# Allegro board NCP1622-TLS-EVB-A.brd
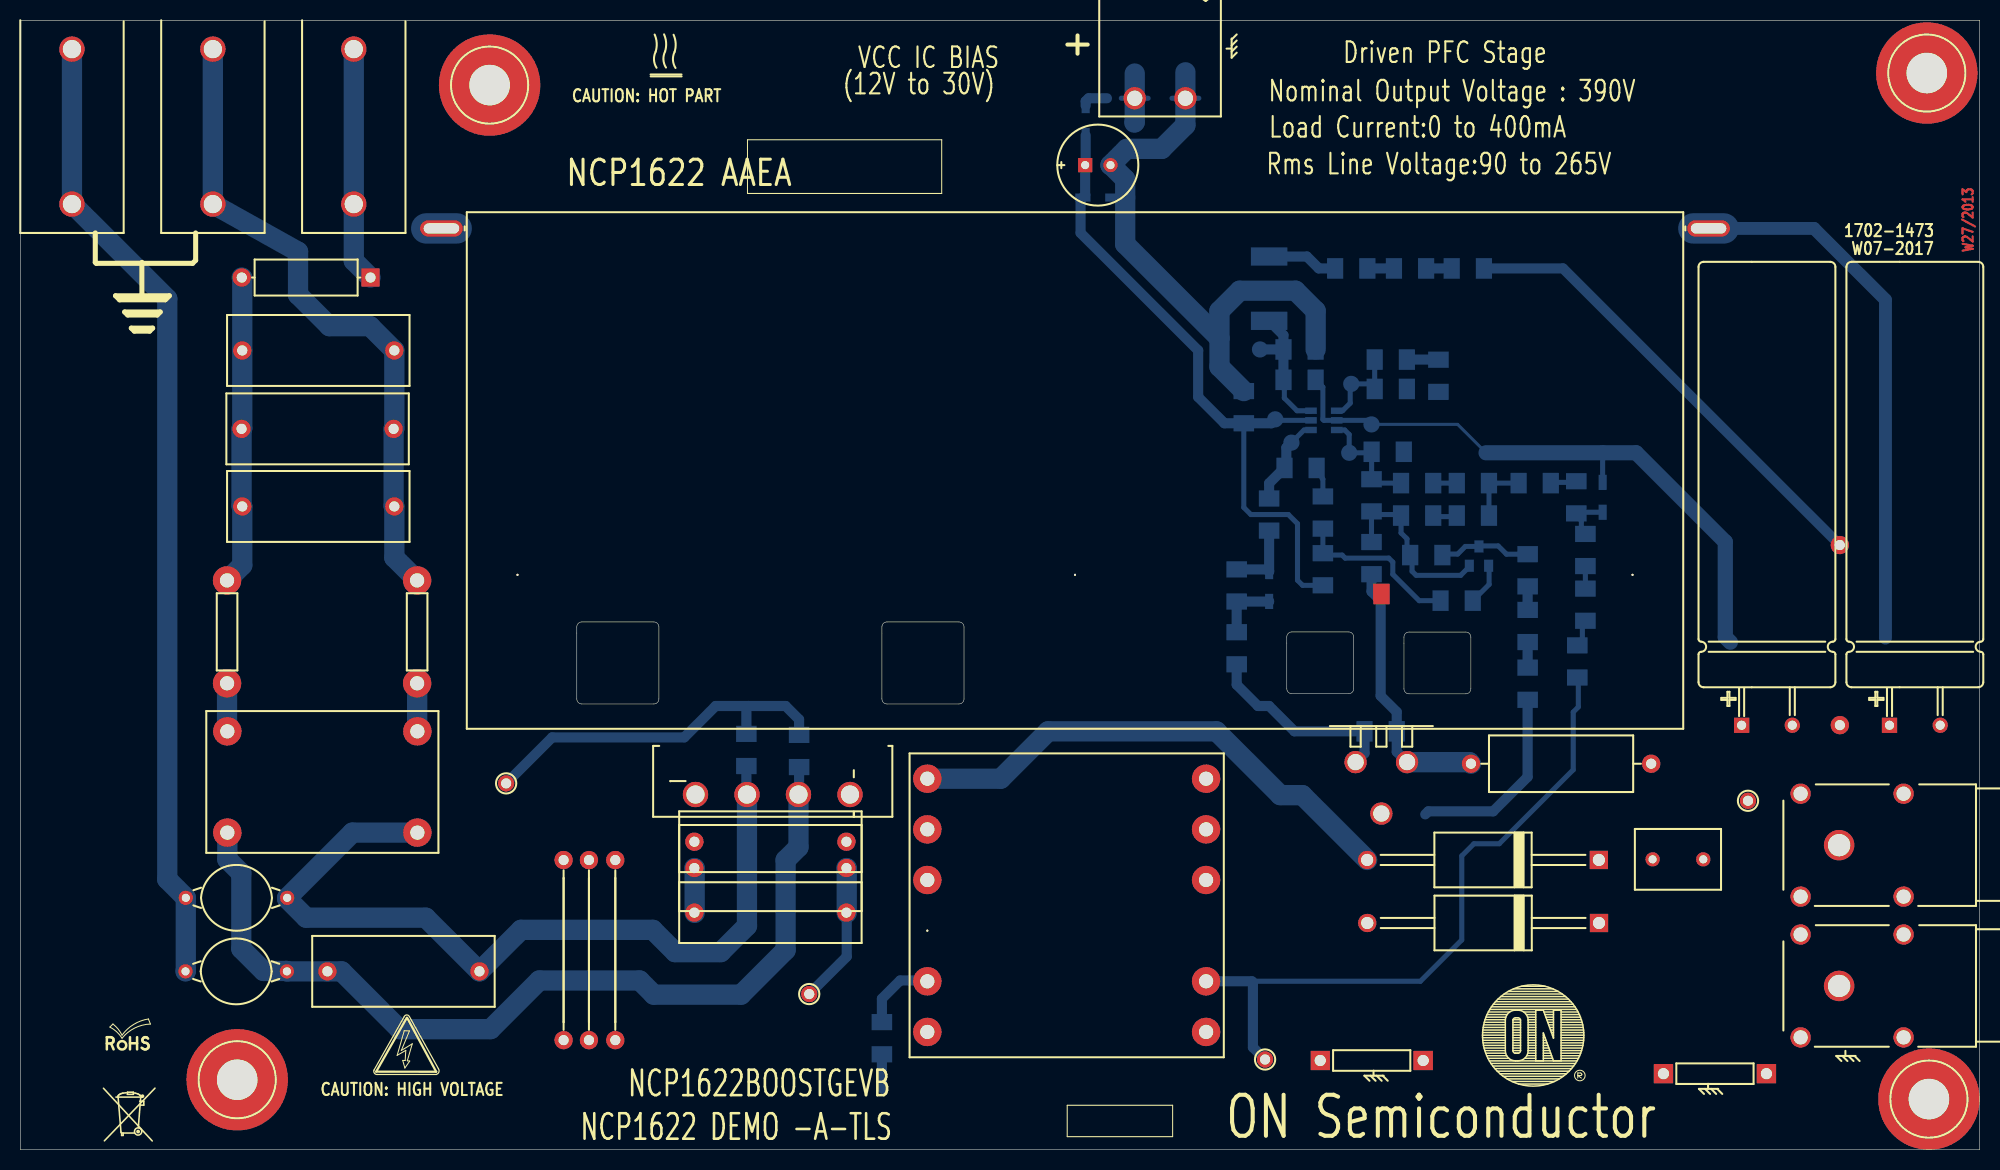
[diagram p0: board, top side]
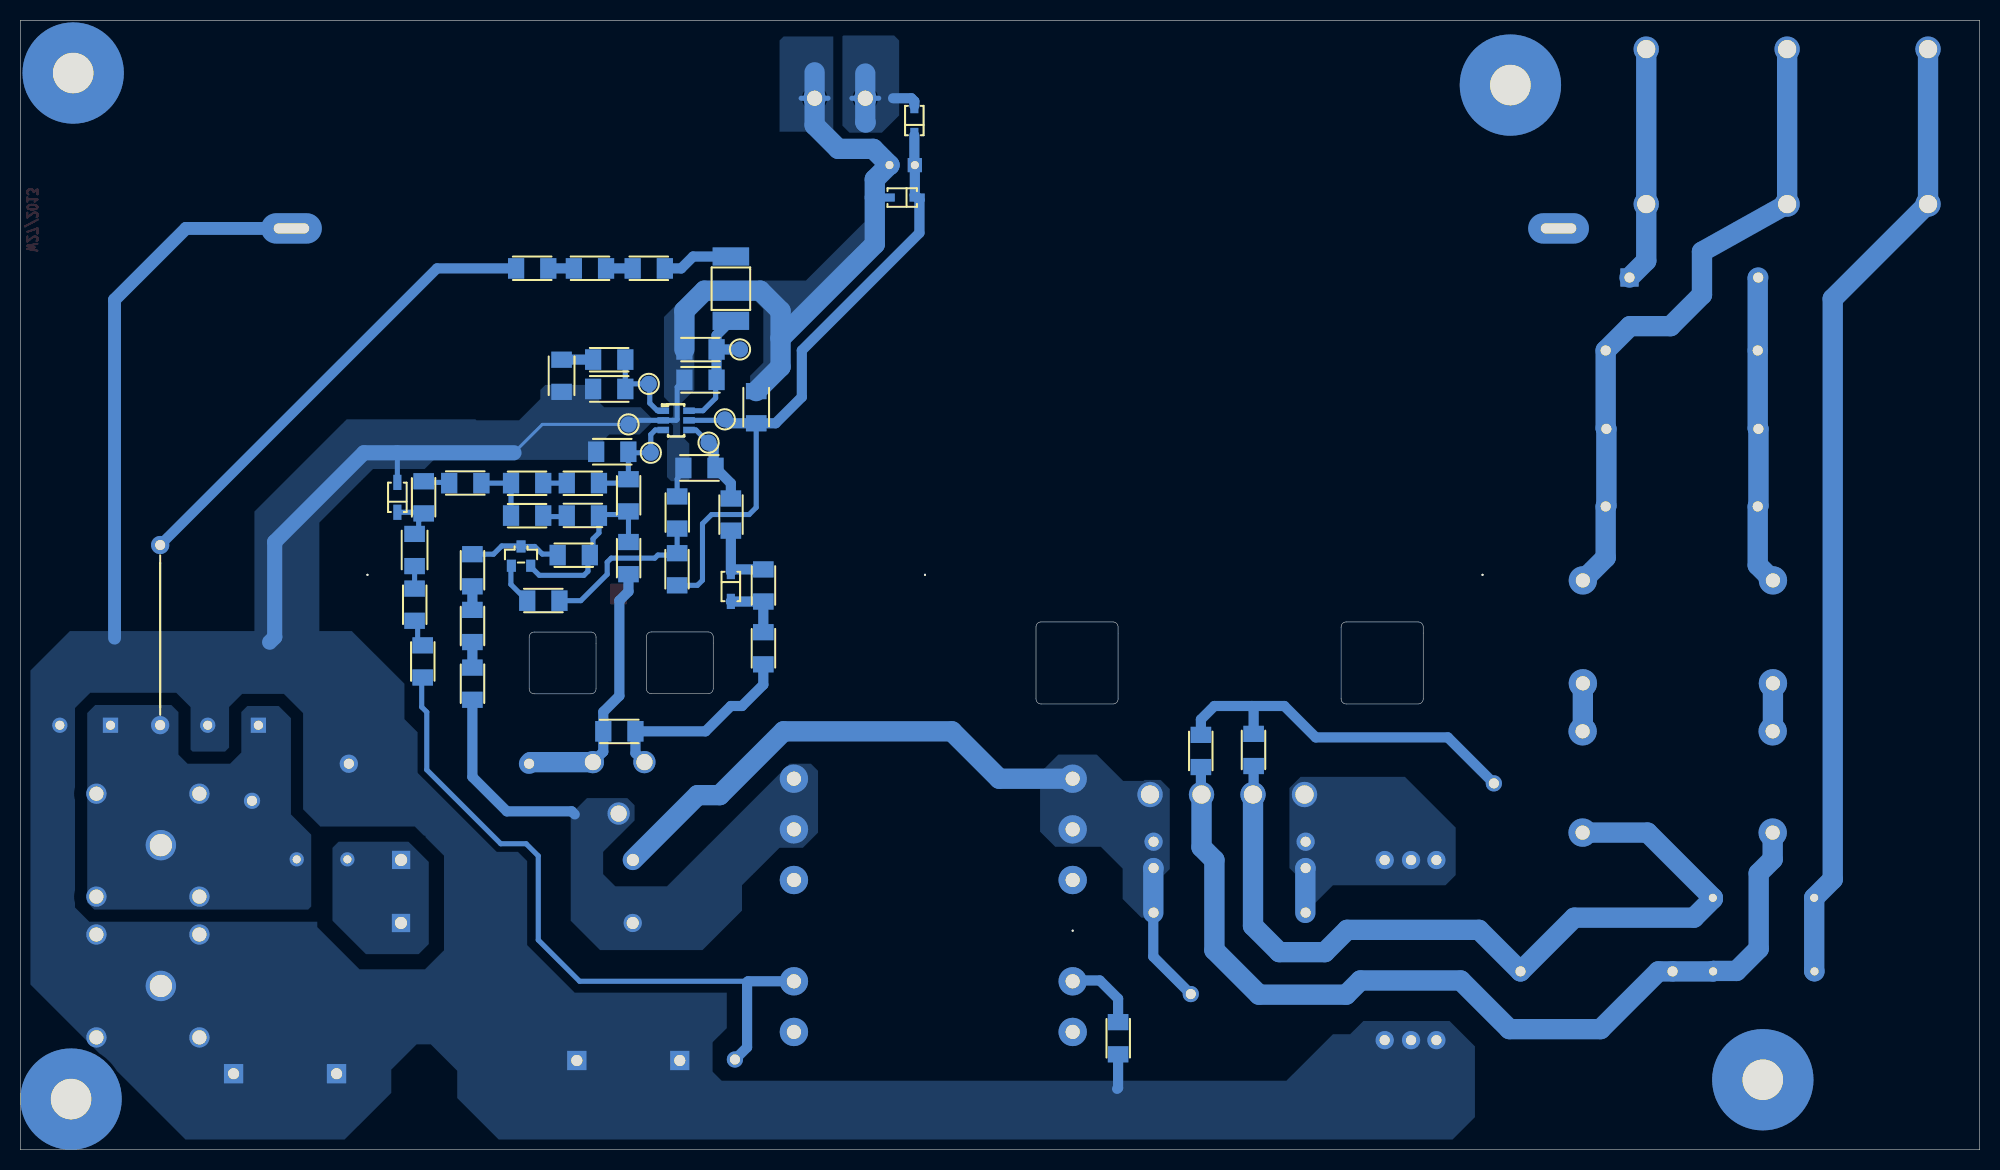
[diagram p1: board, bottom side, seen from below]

Outline 193.3 x 111.5 mm; copper layers: TOP, IN1, IN2, BOTTOM. Coordinates in mm from the lower left corner of the outline.
Outline path: 0,111.5 0,0 193.3,0 193.3,111.5 0,111.5 ; 54.9,51.6 arc(55.05,51.95) 55.4,52.1 62.5,52.1 arc(62.85,51.95) 63,51.6 63,44.5 arc(62.85,44.15) 62.5,44 55.4,44 arc(55.05,44.15) 54.9,44.5 54.9,51.6 ; 85,51.6 arc(85.15,51.95) 85.5,52.1 92.6,52.1 arc(92.95,51.95) 93.1,51.6 93.1,44.5 arc(92.95,44.15) 92.6,44 85.5,44 arc(85.15,44.15) 85,44.5 85,51.6 ; 124.94,50.61 arc(125.09,50.97) 125.44,51.11 131.04,51.11 arc(131.39,50.97) 131.54,50.61 131.54,45.51 arc(131.39,45.16) 131.04,45.01 125.44,45.01 arc(125.09,45.16) 124.94,45.51 124.94,50.61 ; 136.5,50.6 arc(136.65,50.95) 137,51.1 142.6,51.1 arc(142.95,50.95) 143.1,50.6 143.1,45.5 arc(142.95,45.15) 142.6,45 137,45 arc(136.65,45.15) 136.5,45.5 136.5,50.6

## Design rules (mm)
net group MASSE: nets DRV EARTH
net group PHASE1: nets PH1
net group PHASE2: nets PH2

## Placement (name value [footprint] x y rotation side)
C1  1nF/Y  [CAPA_DISK_D7_E7_P10]  21.3 17.6 0 top
C2  1nF/Y  [CAPA_DISK_D7_E7_P10]  21.33 24.86 180 top
C3A  220nF/X2  [CAPA_E7XL18_H13_P15]  29.4 78.9 180 top
C3B  220nF/X2  [CAPA_E7XL18_H13_P15]  29.4 63.5 180 top
C3C  220nF/X2  [CAPA_E7XL18_H13_P15]  29.33 71.16 180 top
C4  220nF/X2  [CAPA_E7XL18_H13_P15]  37.8 17.6 0 top
C5  470nF  [CAPA_E8-5XL18_H14-5_P15]  74 27.8 180 top
C5A  220nF  [CAPA_E6XL18_H11_P15]  74 30.4 180 top
C5B  220nF  [CAPA_E6XL18_H11_P15]  74 23.4 180 top
C6A  68uF  [CAPA_ALU_D12-5_H40_P5_C]  186.9 41.9 90 top
C6B  68uF  [CAPA_ALU_D12-5_H40_P5_C]  172.31 41.9 90 top
C7  22uF  [CAPA_CH_D8_H5_P2-5]  106.3 97.2 0 top
C8  1nF  [1206]  126.2 76 180 bottom
C9  2.2uF  [1206]  139.9 76.4 90 bottom
C10  220nF  [1206]  135.2 75.1 180 bottom
C11  NC  [1206]  134.9 68.9 180 bottom
C12  NC  [1206]  126.3 67.3 180 bottom
C13  100nF  [1206]  120.7 73.3 270 bottom
C30  1nF  [1206]  154.4 59.2 270 bottom
CM1  2x10mH  [SELF__WE_CMC750341634]  29.8 36.3 180 top
CSZCD  TEST POINT  [TP_150_SM]  131.1 68.8 90 bottom
D1  MUR550  [DO201AD]  144.31 22.38 180 top
D2  1N5406  [DO201AD]  144.3 28.6 180 top
D3  1N4148  [SOD123]  123.2 55.6 270 bottom
D4  1N4148  [SOD123]  105.1 101.6 90 bottom
D5  0R  [SMD1206]  153.5 64.4 270 bottom
D6  1N4148  [SOD123]  156.1 64.4 90 bottom
DRV  TEST POINT  [TP_150_SM]  125.4 69.8 90 bottom
DZ2  MMSZ33T1  [SOD123]  106.3 94 0 bottom
EARTH  571-Yelow  [CONN_BANANE-4MM_571]  5.1 101 90 top
F1  4A-250V  [RES_AXI_3-5X10]  28.2 86.1 180 top
FB  TEST POINT  [TP_150_SM]  122.3 79 90 bottom
GND  TEST POINT  [TP_150_SM]  133.3 71.6 90 bottom
HS1  Heatsink_KL_195  [DISIPATEUR_TP207ST_SP]  44.05 41.55 0 top
J4  MSTBA_2_508  [CON_MSTBA_2_508_C]  112.4 103.8 180 top
L  571-black  [CONN_BANANE-4MM_571]  32.9 101 90 top
L2  200uH  [TRANSFO_WE_750370081_EFD30]  103.23 24.12 180 top
N  571-blue  [CONN_BANANE-4MM_571]  19 101 90 top
NOREF  -  []  -73.87 -11.06 0 top
NOREF#2  -  [unnamed#2]  21.4 6.9 0 top
NOREF#3  -  [unnamed#2]  188.29 4.99 0 top
NOREF#4  -  []  0 111.5 0 top
NOREF#5  -  []  -0.7 0 90 top
NOREF#6  -  []  131.1 54.6 0 top
NOREF#7  -  [unnamed#2]  188.08 106.29 0 top
NOREF#8  -  []  78.8 52.7 0 top
NOREF#9  -  [unnamed#2]  46.3 105.1 0 top
NOREF#10  -  []  -164.96 -15.11 0 top
NOREF#11  -  []  294.51 -23.26 180 bottom
P1  SLB4-I/90_R  [BANANE_4MM_SLB4]  179.43 30.06 0 top
P2  SLB4-I/90_B  [BANANE_4MM_SLB4]  179.43 16.16 0 top
Q1  IPA50R250CP  [TO220_C]  131.73 38.26 0 top
Q2  BSS127  [SOT23]  143.9 58.6 0 bottom
R1  1000k  [SMD1206]  71.63 39.46 270 bottom
R2  1000k  [SMD1206]  76.83 39.36 270 bottom
R3  80mR  [RES_LVR03]  152 38.1 0 top
R4  10k  [SMD1206]  134.2 41.3 180 bottom
R5  2.2R  [SMD1206]  120 49.5 90 bottom
R6  22R  [SMD1206]  120 55.7 90 bottom
R7  0R  [SMD1206]  123.2 62.7 90 bottom
R8  680k  [SMD1206]  142.8 87 0 bottom
R9  1800k  [SMD1206]  137.1 87 0 bottom
R10  1800k  [SMD1206]  131.3 87 0 bottom
R11  27k  [SMD1206]  126.2 79 180 bottom
R12  22k  [SMD1206]  135.2 78 180 bottom
R21  47k  [SMD1206]  133.3 58.4 90 bottom
R22  5.1M  [SMD1206]  148.7 46 90 bottom
R23  240K  [SMD1206]  148.7 51.7 90 bottom
R24  240K  [SMD1206]  148.7 57.2 90 bottom
R27  0R  [2512]  123.2 85 270 bottom
R30  0R  [SMD1206]  138.7 58.7 180 bottom
R31  0R  [SMD1206]  133.3 64.6 90 bottom
R32  4.7M  [SMD1206]  128.5 62.9 90 bottom
R33  1M  [SMD1206]  128.5 57.3 270 bottom
R34  NC  [SMD1206]  137.8 62.6 0 bottom
R36  NC  [SMD1206]  137.8 65.8 180 bottom
R37  27k  [SMD1206]  143.3 65.8 180 bottom
R38  22k  [SMD1206]  143.3 62.6 180 bottom
R39  270K  [SMD1206]  149.4 65.8 0 bottom
R40  100R  [SMD1206]  154.4 53.8 90 bottom
R41  NC  [SMD1206]  153.6 48.2 90 bottom
R42  NC  [SMD1206]  141.7 54.2 0 bottom
RTH1  B57153S150M  [DISK_D8-5_E6_P5]  163.53 28.66 0 top
RZ  0R  [SMD1206]  85 11 90 bottom
S1A  Strap  [JUMPER400H]  138.4 8.8 180 top
S1B  Strap  [JUMPER400H]  162.1 7.5 0 top
S2A  Strap  [JUMPER400H]  20.4 56.2 270 top
S2B  Strap  [JUMPER400H]  39.15 56.2 270 top
S3  Strap  [STRAP_FIL_700]  179.5 50.8 90 bottom
S4A  Strap  [STRAP_FIL_700]  53.6 19.7 270 top
S4B  Strap  [STRAP_FIL_700]  56.1 19.7 270 top
S4C  Strap  [STRAP_FIL_700]  58.7 19.7 270 top
U1  GBU406  [PONT_RD_GBU_C]  74.23 35.06 0 top
U2  NCP1602  [SOT23-6]  128.6 72 270 bottom
VAUX  TEST POINT  [TP_T1]  122.8 8.9 0 top
VBULK  TEST POINT  [TP_T1]  170.44 34.44 0 top
VCC  TEST POINT  [TP_150_SM]  123.8 72.1 90 bottom
VCTRL  TEST POINT  [TP_150_SM]  131.3 75.6 90 bottom
VIN  TEST POINT  [TP_T1]  77.83 15.36 0 top
VLINE  TEST POINT  [TP_T1]  47.93 36.16 0 top

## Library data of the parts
C1 C2 C3A C3B C3C C4 C5 C5A C5B C8-C13 C30 = C
C6A C6B = C_elect_1
C7 = C_elect_0
CM1 = WE-CMB_2
CSZCD DRV FB GND S1A S1B S2A S2B S3 S4A S4B S4C VAUX VBULK VCC VCTRL VIN VLINE = TEST POINT_0
D1-D4 D6 = D1N4937
D5 R1-R12 R21-R24 R27 R30-R34 R36-R42 RZ = R
DZ2 = zener_sot23_0
EARTH L N = HEADER 1_1
F1 = FUSE
HS1 = Heatsink_KL_195
J4 = HEADER 2_0
L2 = RN114-0_5.8/02
P1 P2 = HEADER 1_0
Q1 = NMOS_3
Q2 = NMOS_4
RTH1 = THERMISTOR_0
U1 = KBUxK_1
U2 = NCP1602

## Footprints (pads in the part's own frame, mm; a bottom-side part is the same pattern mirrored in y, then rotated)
1206
  rect 1.6x2.03 smd: 1(-1.587,0) 2(1.587,0)
2512
  rect 1.8x3.6 smd: 1(-3.175,0) 2(3.175,0)
BANANE_4MM_SLB4
  round 3 hole 2.2: 1(0,0)
  round 2 hole 1.4: 2(-3.8,5.08) 3(-3.8,-5.08) 4(6.36,5.08) 5(6.36,-5.08)
CAPA_ALU_D12-5_H40_P5_C
  rect 1.5x1.5 hole 0.9: 1(0,2.5)
  round 1.5 hole 0.9: 2(0,-2.5)
CAPA_CH_D8_H5_P2-5
  rect 1.4x1.4 hole 0.8: 1(-1.25,0)
  round 1.4 hole 0.8: 2(1.25,0)
CAPA_DISK_D7_E7_P10
  round 1.4 hole 0.8: 1(-5,0) 2(5,0)
CAPA_E6XL18_H11_P15
  round 1.8 hole 1: 1(7.5,0) 2(-7.5,0)
CAPA_E7XL18_H13_P15
  round 1.8 hole 1: 1(7.5,0) 2(-7.5,0)
CAPA_E8-5XL18_H14-5_P15
  round 1.8 hole 1: 1(7.5,0) 2(-7.5,0)
CON_MSTBA_2_508_C
  round 2.2 hole 1.5: 1(2.46,0) 2(-2.54,0)
CONN_BANANE-4MM_571
  round 2.5 hole 1.8: 1(-7.65,0) 2(7.65,0)
DISIPATEUR_TP207ST_SP
  round 0.2 hole 3.2 unplated: (5,15.2) (60,15.2) (115,15.2)
  oval 4.2x1.6 hole 3.5x1: 1(-2.5,49.4) 2(122.5,49.4)
DISK_D8-5_E6_P5
  round 1.4 hole 0.8: 1(-2.5,0) 2(2.5,0)
DO201AD
  round 1.8 hole 1.2: 1(11.43,0)
  rect 1.8x1.8 hole 1.2: 2(-11.43,0)
JUMPER400H
  round 2.8 hole 1.4: 1(0,0) 2(10.16,0)
PONT_RD_GBU_C
  round 2.5 hole 1.8: 1(7.62,0) 2(2.54,0) 3(-2.54,0) 4(-7.62,0)
RES_AXI_3-5X10
  rect 1.8x1.8 hole 1: 1(-6.35,0)
  round 1.8 hole 1: 2(6.35,0)
RES_LVR03
  round 1.8 hole 1: 1(-8.89,0) 2(8.89,0)
SELF__WE_CMC750341634
  round 2.8 hole 1.4: 1(-9.375,5) 2(-9.375,-5) 3(9.375,-5) 4(9.375,5)
SMD1206
  rect 1.6x2.03 smd: 1(-1.587,0) 2(1.587,0)
SOD123
  rect 1.5x0.8 smd: 1(1.475,0) 2(-1.475,0)
SOT23
  rect 0.9x1.2 smd: 1(0.953,0.953) 2(-0.953,0.953) 3(0,-0.953)
SOT23-6
  rect 0.64x1.15 smd: 1(-0.953,-1.27) 2(0,-1.27) 3(0.953,-1.27) 4(0.953,1.27) 5(0,1.27) 6(-0.953,1.27)
STRAP_FIL_700
  round 1.8 hole 1: 1(-8.89,0) 2(8.89,0)
TO220_C
  rect 1.6x2.03 smd: (2.54,16.6)
  round 2.2 hole 1.6: 1(0,0) 2(2.54,-5.08) 3(5.08,0)
TP_150_SM
  round 1.6 smd: 1(0,0)
TP_T1
  round 1.6 hole 1: 1(0,0)
TRANSFO_WE_750370081_EFD30
  round 0.2 hole 1 unplated: (13.75,2.5)
  round 2.8 hole 1.4: 1(-13.75,12.5) 2(-13.75,7.5) 4(-13.75,-2.5) 5(-13.75,-7.5) 6(-13.75,-12.5) 7(13.75,-12.5) 8(13.75,-7.5) 9(13.75,-2.5) 11(13.75,7.5) 12(13.75,12.5)
unnamed#2
  round 10 hole 4: 1(0,0)

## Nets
GND_EARTH: C6A.2(-) C6B.2(-) C7.2(-) C8.1 C9.1 C10.1 C11.1 C12.1 C13.1 D6.1 DZ2.1(ANODE) GND.1 HS1.2 J4.2 P2.1 P2.2 P2.3 P2.4 P2.5 R3.2 R11.1 R32.2 RZ.1 S1A.1 S1A.2 S1B.1 S1B.2 S4A.2 S4B.2 S4C.2 U2.2(GND)
VCC: C7.1(+) C13.2 D4.2 DZ2.2(CATHODE) R33.2 U2.5(VCC) VCC.1
VIN: C5.2 C5A.2 C5B.2 D2.1 L2.7 L2.8 U1.1(+) VIN.1
CSZCD: C11.2 CSZCD.1 R31.2 R36.2 U2.3(CS/ZCD)
DRIVE: D3.2 R6.2 R7.1
DRV: C12.2 DRV.1 R7.2 U2.4(DRV)
EARTH: C1.1 C2.2 EARTH.1 EARTH.2
FB: C8.2 FB.1 R11.2 R27.2 U2.6(FB)
LINE: F1.1 L.1 L.2
NEUTRAL: C3A.2 C3B.2 C3C.2 N.1 N.2 S2B.1
PH1: C1.2 C4.2 CM1.4 R2.2 U1.2(AC1)
PH2: C2.1 C4.1 CM1.1 R1.2 U1.3(AC2)
VAUX: L2.2 R41.1 VAUX.1
VBULK: C6A.1(+) C6B.1(+) P1.1 P1.2 P1.3 P1.4 P1.5 RTH1.2 S3.1 VBULK.1
VCTRL: C10.2 R12.2 U2.1(VCTRL) VCTRL.1
VDRAIN: D1.1 L2.5 L2.6 Q1.2(D) R22.1
VLINE: R1.1 R2.1 VLINE.1
VSOURCE: Q1.3(S) R3.1 R4.1 R21.1
N292537: CM1.3 S2A.2
N698273: CM1.2 S2B.2
N12234995: C3A.1 C3B.1 C3C.1 F1.2 S2A.1
N12236480: C5.1 C5A.1 C5B.1 S4A.1 S4B.1 S4C.1 U1.4(-)
N12238080: D1.2 D2.2 RTH1.1
N12238999: Q1.1(G) R4.2 R5.1
N12239079: D3.1 R5.2 R6.1
N12239384: D4.1 J4.1
N12240791: C9.2 R12.1
N12241323: Q2.2(S) R21.2 R30.2 R31.1 R34.1
N12242862: R23.2 R24.1
N12244725: R8.2 S3.2
N12257162: L2.11 RZ.2
N12257918: R9.1 R10.2
N12257928: R8.1 R9.2
N12261898: Q2.3(D) R24.2 R30.1
N12263431: C30.1 D5.2 D6.2
N12264127: R37.1 R38.1 R39.1
N12264132: R34.2 R38.2
N12264252: R36.1 R37.2
N12264429: R32.1 R33.1 R42.1
N12264457: Q2.1(G) R42.2
N122408501: R22.2 R23.1
N122410581: R40.1 R41.2
N122446060: R10.1 R27.1
N122633001: C30.2 R40.2
N122636271: D5.1 R39.2

Pads without a net: HS1 1; L2 1 4 9 12; NOREF#2 1; NOREF#3 1; NOREF#7 1; NOREF#9 1

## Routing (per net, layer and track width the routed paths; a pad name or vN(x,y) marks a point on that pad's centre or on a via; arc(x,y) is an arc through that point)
GND_EARTH: length 184.6
  BOTTOM w0.3: DZ2.1 109,94 ; GND.1 141.8,71.6 144.6,68.8
  BOTTOM w0.5: R32.2 128.5,66.2 128.4,66.3 ; 116.27,103.8 J4.2 113.61,103.8 ; D6.1 156.1,68.8 ; C8.1 128.5,75.29 128.5,72.1 128.6,72 U2.2 132.9,72 GND.1
  BOTTOM w1: RZ.1 85,6.1 85.1,6
  BOTTOM w1.27: 184,50.5 184,83.9 176.95,90.95 HS1.2
  BOTTOM w1.5: 168.7,50.1 168.2,50.6 168.2,60 159.4,68.8 144.6,68.8
  BOTTOM w2: C13.1 118.3,77.29 118.3,80.1 ; 118.3,80.1 109,89.4 109,95.8 107.6,97.2 C7.2 109.15,98.8 112.6,98.8 114.94,101.14 J4.2 114.94,106.36 ; 118.3,80.1 118.3,82.8 120.3,84.8 125.8,84.8 127.79,82.81 R11.1
VCC: length 65.8
  BOTTOM w0.5: R33.2 126.5,55.71 126,56.21 126,61.8 125.1,62.7 121.4,62.7 120.7,63.4 C13.2 ; VCC.1 123.9,72 U2.5
  BOTTOM w1: VCC.1 123.41,71.71 C13.2 118.79,71.71 116.2,74.3 116.2,78.9 104.6,90.5 104.6,93.78 DZ2.2 105.05,94.22 C7.1 105.1,97.25 D4.2
VIN: length 64.6
  BOTTOM w1: 81.53,23.37 81.53,19.06 VIN.1
  BOTTOM w2: D2.1 126.47,35 124.3,35 118,41.3 101.4,41.3 96.72,36.62 L2.7 ; 81.53,23.37 81.53,27.77 C5.2
CSZCD: length 11.5
  BOTTOM w0.5: U2.3 130.65,71.05 131.1,70.6 CSZCD.1 133.21,68.8 C11.2 133.31,66.1 R31.2 133.59,65.8 R36.2
DRIVE: length 7.3
  BOTTOM w1: R7.1 D3.2 122.99,57.29 R6.2
DRV: length 8.9
  BOTTOM w0.5: U2.4 126.65,71.05 DRV.1
  BOTTOM w1: R7.2 123.2,65.79 C12.2 124.9,67.49 124.9,69.3 DRV.1
EARTH: length 95.7
  BOTTOM w2: EARTH.2 EARTH.1 5.15,93.35 14.5,84 14.5,26.69 C2.2 16.33,17.63 C1.1
FB: length 13.7
  BOTTOM w0.5: C8.2 124.7,75.91 124.7,74.2 125.95,72.95 U2.6
  BOTTOM w1: R11.2 124.61,80.41 R27.2 ; R11.2 C8.2 ; R11.2 FB.1
LINE: length 23.2
  BOTTOM w2: F1.1 32.9,87.75 L.1 L.2
NEUTRAL: length 64.6
  BOTTOM w2: N.2 N.1 27.4,88.65 27.4,84.4 30.5,81.3 34.5,81.3 C3A.2 36.9,71.23 C3C.2 36.83,63.57 C3B.2 36.9,58.45 S2B.1
PH1: length 92
  BOTTOM w1: R2.2 76.83,35.12 U1.2
  BOTTOM w2: U1.2 76.77,29.86 75.5,28.59 75.5,19.7 71.1,15.3 62.5,15.3 61.1,16.7 51.2,16.7 46.4,11.9 37.4,11.9 31.7,17.6 C4.2 C1.2 26.26,17.64 24,17.64 21.8,19.83 21.8,27.29 20.43,28.67 CM1.4
PH2: length 83.4
  BOTTOM w1: U1.3 71.63,35.12 R1.2
  BOTTOM w2: CM1.1 32.77,31.3 C2.1 26.33,24.77 28.2,22.9 40,22.9 C4.1 49.4,21.7 62.4,21.7 64.6,19.5 69.1,19.5 71.69,22.09 U1.3
VAUX: length 67.4
  BOTTOM w0.5: R41.1 153.7,46.51 153.7,43.7 153.2,43.2 153.2,37.5 145.9,30.2 143.4,30.2 142.2,29 142.2,20.7 138.12,16.62 121.5,16.62
  BOTTOM w1: VAUX.1 121.6,10.1 121.6,16.52 121.5,16.62 L2.2
VCTRL: length 9
  BOTTOM w0.5: R12.2 C10.2 133.11,75.6 VCTRL.1 131.2,75.5 131.2,73.7 130.45,72.95 U2.1
VDRAIN: length 19.2
  BOTTOM w1: 138.6,33.1 138.9,33.4 145.3,33.4 148.7,36.8 R22.1
VLINE: length 37
  BOTTOM w1: R2.1 76.83,42.47 75.5,43.8 71.8,43.8 ; R1.1 71.63,43.63 71.8,43.8 ; VLINE.1 52.47,40.7 65.5,40.7 68.6,43.8 71.8,43.8
VSOURCE: length 26.4
  BOTTOM w1: Q1.3 135.79,39.28 R4.1 135.79,43.21 134.2,44.8 134.2,54.2 133.3,55.1 R21.1
  BOTTOM w2: R3.1 142.95,38.26 Q1.3
N292537: length 4.8
  BOTTOM w2: CM1.3 20.4,41.33 S2A.2
N698273: length 4.8
  BOTTOM w2: S2B.2 39.15,41.33 CM1.2
N12234995: length 30.6
  BOTTOM w2: S2A.1 21.9,57.7 C3B.1 21.83,63.57 C3C.1 21.9,71.23 C3A.1 21.9,86.05 F1.2
N12236480: length 4.5
  BOTTOM w0.3: 66.53,23.37 C5B.1
  BOTTOM w2: C5.1 66.53,27.77 66.53,23.37
N12238999: length 19.9
  BOTTOM w1: R5.1 120,45.9 122.1,43.8 123.2,43.8 125.7,41.3 R4.2 132.61,39.14 Q1.1
N12239079: length 6.2
  BOTTOM w1: D3.1 123.19,54.11 R6.1 R5.2
N12239384: length 10.2
  BOTTOM w0.5: 108.61,103.8 J4.1 111.27,103.8
  BOTTOM w1: 107.2,103.8 105.4,103.8 105.1,103.5 105.1,103.08
  BOTTOM w2: 109.94,106.24 J4.1 109.94,101.44 109.9,101.4
N12240791: length 3.1
  BOTTOM w1: R12.1 139.89,78 C9.2
N12241323: length 18.4
  BOTTOM w0.5: Q2.2 142.95,57.55 142.1,56.7 137.7,56.7 137.3,57.1 137.3,58.51 R30.2 136.8,59.01 136.8,60.3 136.21,60.89 R34.1 136.11,62.7 133.51,62.7 R31.1 R21.2
N12242862: length 2.3
  BOTTOM w1: R23.2 R24.1
N12244725: length 46.4
  BOTTOM w1: R8.2 152.19,87 S3.2
N12257162: length 7.6
  BOTTOM w1: L2.11 89.4,16.7 86.8,16.7 85,14.9 RZ.2
N12257918: length 2.6
  BOTTOM w1: R10.2 R9.1
N12257928: length 2.5
  BOTTOM w1: R9.2 R8.1
N12261898: length 9.1
  BOTTOM w0.5: R24.2 146.61,58.79 145.8,59.6 143.95,59.6 Q2.3 142.55,59.55 141.8,58.8 140.39,58.8 R30.1
N12263431: length 5.1
  BOTTOM w0.5: C30.1 154.4,60.8 154,61.2 154,62.1 153.5,62.6 D5.2 153.5,62.83 153.6,62.92 156.1,62.92
N12264127: length 6.3
  BOTTOM w0.5: R39.1 R37.1 R38.1 144.89,62.4
N12264132: length 2.4
  BOTTOM w0.5: R38.2 141.61,62.5 139.49,62.5 R34.2
N12264252: length 2.3
  BOTTOM w0.5: R37.2 R36.1
N12264429: length 16.7
  BOTTOM w0.5: R32.1 R33.1 128.69,58.7 130.4,58.7 130.7,58.4 135,58.4 135.4,58 135.4,56.8 138,54.2 R42.1
N12264457: length 4.1
  BOTTOM w0.5: R42.2 143.3,54.2 144.9,55.8 144.9,57.6 Q2.1
N122408501: length 2.5
  BOTTOM w1: R22.2 R23.1
N122410581: length 2.8
  BOTTOM w0.3: 154.1,50.2 153.69,49.79 R41.2
  BOTTOM w0.5: R40.1 154.1,51.91 154.1,50.2
N122446060: length 7
  BOTTOM w1: R27.1 126.92,88.17 128.1,87 R10.1
N122633001: length 2.2
  BOTTOM w0.5: R40.2 C30.2
N122636271: length 2.6
  BOTTOM w0.5: R39.2 151.06,65.88 153.39,65.88 D5.1

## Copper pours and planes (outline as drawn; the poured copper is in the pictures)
GND_EARTH on BOTTOM: 52,1 49.8,3.2 49.8,10.2 52.3,12.7 60.8,12.7 62.1,11.4 63.8,11.4 68.4,6.8 124.1,6.8 125,7.7 125,10.6 123.6,12 123.6,15.5 138.6,15.5 143.3,20.2 143.3,28.5 144.2,29.4 146.3,29.4 154.1,37.2 154.1,41.2 155.4,42.5 155.4,46 160.6,51.2 188.4,51.2 192.3,47.3 192.3,16.3 177,1 161.3,1 156.7,5.6 156.7,7.9 154.2,10.4 152.8,10.4 150.2,7.8 150.2,5.1 146.1,1 ; 2 cut-outs
GND_EARTH on BOTTOM: 113.1,109.9 113.1,99.9 113.3,100.1 114.9,100.1 115.3,100.5 118.4,100.5 118.4,109.5 118,109.9
GND_EARTH on BOTTOM: 144.1,72 142,74.1 142,75 141.5,75.5 136.7,75.5 136.2,75 136.2,73.8 135.7,73.3 132.1,73.3 131,72.2 129.1,72.2 128.9,72.4 128.9,73.4 129.8,74.3 129.8,82.2 126.2,85.8 115.8,85.8 109.7,91.9 108.9,91.9 108.9,89.1 117.9,80.1 117.9,77.4 119.8,75.5 119.8,74.8 120.4,74.2 120.7,74.2 121.3,74.8 121.3,76.4 120,77.7 120,83 120.8,83.8 125.4,83.8 126.8,82.4 126.8,75 128.2,73.6 128.2,70.6 127.3,69.7 127.3,66.2 127.5,66 129.1,66 129.5,66.4 129.5,70 128.9,70.6 128.9,71.5 129.2,71.8 131,71.8 132.2,70.6 135.2,70.6 135.8,70 135.8,68.4 136.1,68.1 146.8,68.1 147.2,68.5 152.1,68.5 153.4,67.2 158.5,67.2 163.8,61.9 163.8,50.6 165.9,48.5 168.7,48.5 170.2,50 170.2,63 161.1,72.1 148.4,72.1 148.3,72
VIN on BOTTOM: 82.4,36.5 80.8,36.5 79.9,35.6 79.9,27.7 80.7,26.9 80.7,23.4 81.2,22.9 82.7,22.9 84.55,24.75 84.55,27.75 86.7,29.9 91.2,29.9 92.7,31.4 92.7,37.2 90.9,39 87.1,39 84.5,36.4 82.5,36.4
VBULK on BOTTOM: 164.6,31.1 164.6,24 164.9,23.7 186,23.7 186.7,24.4 186.7,43.1 185.9,43.9 178.4,43.9 177.7,43.2 177.7,39 176.8,38.1 172.6,38.1 171.5,39.2 171.5,43.2 170.9,43.8 167.8,43.8 166.6,42.6 166.6,33.1
VDRAIN on BOTTOM: 117.4,38.1 115.3,38.1 114.6,37.4 114.6,31.3 116.1,29.8 118.4,29.8 122.1,26.1 122.1,23.6 126,19.7 136.1,19.7 139,22.6 139,33.1 137.4,34.7 133.4,34.7 132.7,34 132.7,32.5 135.8,29.4 135.8,27.2 134.6,26 129.5,26
N12236480 on BOTTOM: 51.7,31.8 51.7,27.1 52.7,26.1 63.8,26.1 65.9,24 67.1,24 67.4,24.3 67.4,27.1 68.1,27.8 68.1,35.7 67,36.8 56.7,36.8
N12238080 on BOTTOM: 154,19.3 159.2,19.3 162.5,22.6 162.5,29.8 161.9,30.4 155,30.4 153,28.4 153,20.3
N12239384 on BOTTOM: 112.2,109.9 112.2,101.1 111.5,100.4 108.3,100.4 106.6,102.1 106.6,109.5 107.1,110 112.1,110

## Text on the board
BOTTOM: BOT 1/2
Ref Des/Silkscreen Bottom: SILK_BOT
User.Comments: VE_BOT | VE_TOP
TOP: TOP 2/2 | W27/2013
Ref Des/Assembly Top: Pate Thermique
Ref Des/Silkscreen Top: CAUTION: HIGH VOLTAGE | SILK_TOP | CAUTION: HOT PART | 1702-1473 | W07-2017 | (12V to 30V) | VCC IC BIAS | Rms Line Voltage:90 to 265V | Nominal Output Voltage : 390V | Load Current:0 to 400mA | Driven PFC Stage | NCP1622 DEMO -A-TLS | NCP1622BOOSTGEVB | NCP1622 AAEA | ON Semiconductor
IN1: IN1 3/4
IN2: IN2 2/4
DIMENSION: S1a ,S1b ,S2a ,S2b | h=6mm
User.10: CHEMICAL NiAu | 35um(1oz)at START | face soudure | Pour les details des 4 ouvertures a detourer , voir le gerber outline.art | THICKNESS | MATERIAL | STACKUP | FINISH | SILKSCREEN | MINIMAL GAP | MINIMAL SLIVER | BOARD THICKNESS | SOLDER MASK | COPPER THICKNESS | MARKED ON BOTTOM SOLDERMASK | ALL BOARD ELECTRICALLY TESTED | MANUFACTURE 'S LOGO & DATECODE | COMPLIANT RoHS DIRECTIVE 2011/65/UE | SF /1LAYER | WHITE TOP&BOT | FR4 IMPROVED (low CTE) | GREEN BOT | 300um /12.0mils | 1.6mm /63mils | SPEC:
User.11: NCP1622-A-TLS-0001 1702-1473   W07/2017
User.12: FIGURE | SIZE | 0.8 | 0.9 | 1.0 | 1.1 | 1.2 | 1.4 | 1.5 | 1.6 | 1.8 | 2.2 | 4.0 | 3.2 | 3.5x1.0 | DRILL CHART: TOP to BOTTOM | ALL UNITS ARE IN MILLIMETERS | PLATED | NON-PLATED | QTY | 8 | 4 | 30 | 26 | 2 | 3 | 10 | 1
